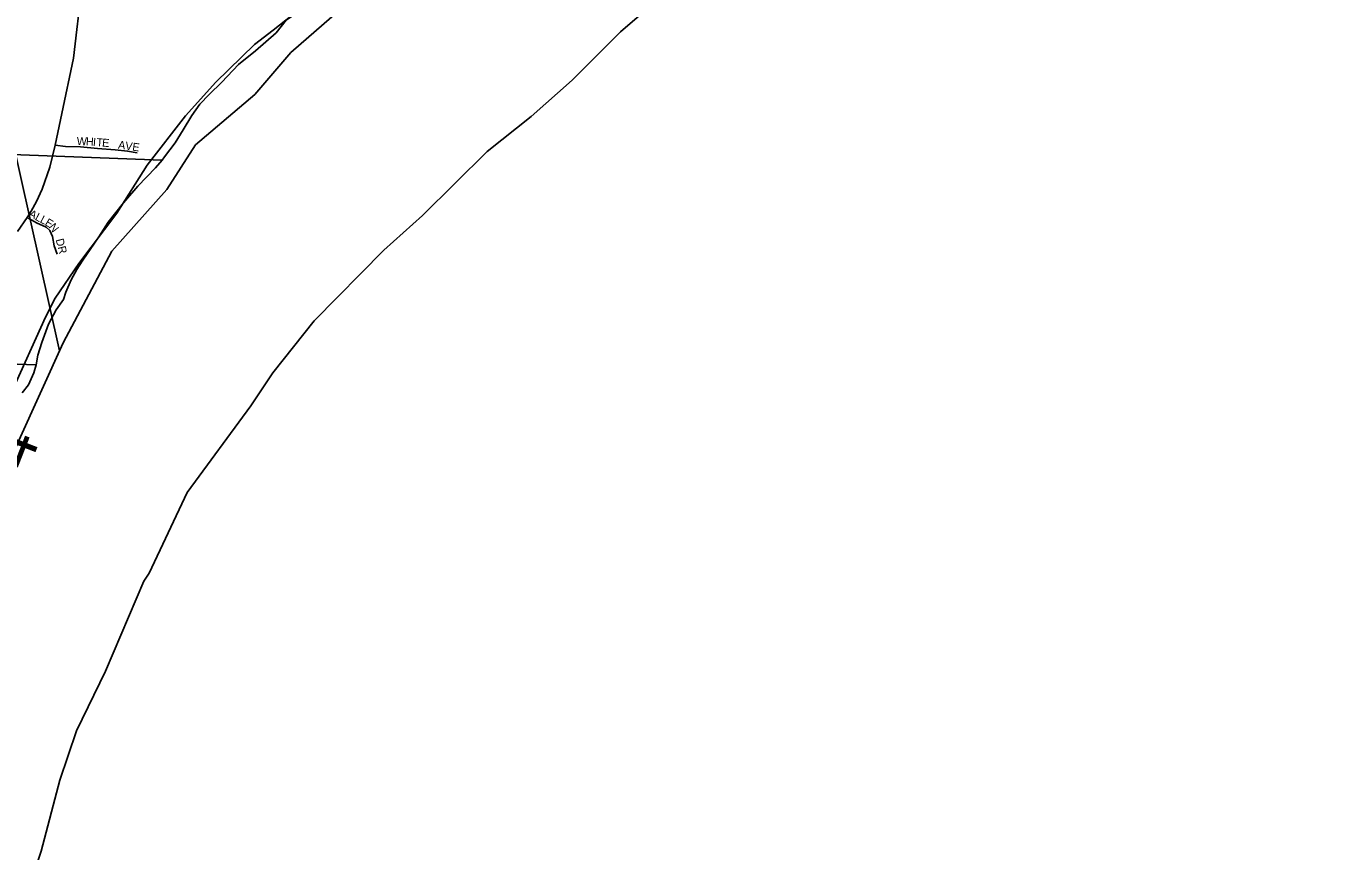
# Model space of a CAD drawing. Extents: x 1878108 to 2183446, y 146837 to 508383.
# Drawn here: x 2048929 to 2057027, y 286848 to 292008 of the extents above; entities that cross this region are included whole.
import ezdxf

# ---------------------------------------------------------------- set-up
doc = ezdxf.new("R2010")
doc.units = 0
for name, color, linetype in [('GM_X_City_Street', 7, 'Continuous'), ('GM_X_City_Street_Text', 7, 'Continuous'), ('GM_X_Corporation', 7, 'Continuous'), ('GM_X_County', 7, 'Continuous'), ('GM_X_County_Road_Text', 7, 'Continuous'), ('GM_X_Major_River', 7, 'Continuous'), ('GM_X_Section', 7, 'Continuous'), ('GM_X_State_Route', 7, 'Continuous'), ('GM_X_Township', 7, 'Continuous')]:
    doc.layers.add(name, color=color, linetype=linetype)

msp = doc.modelspace()

# ---------------------------------------------------------------- linework, layer by layer
at = {"layer": 'GM_X_City_Street'}
for points in [[(2049112, 291262.8), (2049176.3, 291253.7), (2049270.4, 291252.5), (2049376, 291242.2), (2049486.2, 291233), (2049564.2, 291225), (2049622.8, 291214.6)], [(2049123.5, 290580), (2049105.1, 290632.8), (2049094.8, 290690.1), (2049077.6, 290729.2), (2049055.8, 290748.7), (2048993.8, 290777.4), (2048936.4, 290809.5)]]:
    msp.add_lwpolyline(points, dxfattribs=at)
at = {"layer": 'GM_X_Corporation'}
msp.add_lwpolyline([(2057212.1, 297306.5), (2056735.2, 297160.2), (2056232.2, 296817.6), (2055577.6, 296152.3), (2055056.8, 295388.9), (2054757.4, 295136.5), (2053436.3, 294134.7), (2052695.8, 293625.8), (2052328.6, 293317.2), (2051352.7, 292511.8), (2050584.3, 291840.6), (2050358.8, 291578.1), (2049987.6, 291263.6), (2049808, 290985.1), (2049464.7, 290598.4), (2049161.4, 290025.3), (2049139.4, 289977), (2048708.6, 291891.2)], dxfattribs=at)
at = {"layer": 'GM_X_County'}
msp.add_lwpolyline([(2057212.1, 297306.5), (2056735.2, 297160.2), (2056232.2, 296817.6), (2055577.6, 296152.3), (2055056.8, 295388.9), (2054757.4, 295136.5), (2053436.3, 294134.7), (2052695.8, 293625.8), (2052328.6, 293317.2), (2051352.7, 292511.8), (2050584.3, 291840.6), (2050358.8, 291578.1), (2049987.6, 291263.6), (2049808, 290985.1), (2049464.7, 290598.4), (2049161.4, 290025.3), (2048195.4, 287901.3), (2047973.9, 287198), (2047804.2, 286626.9)], dxfattribs=at)
at = {"layer": 'GM_X_Major_River'}
msp.add_line((2050671.3, 292137), (2050474.3, 291981.8), dxfattribs=at)
for points in [[(2048939.1, 286593.9), (2049023.9, 286848.8), (2049139.9, 287292.2), (2049244.4, 287599.3), (2049426.6, 287972.9), (2049665.8, 288535.1), (2049697.6, 288585.4), (2049937, 289089.4), (2050334.1, 289632.2), (2050470.9, 289839.2), (2050729.1, 290163), (2051164.5, 290605.7), (2051407.1, 290823.2), (2051810.7, 291221.7), (2052085.2, 291441.2), (2052341.8, 291668.8), (2052643.9, 291970.7), (2053000, 292278.8)], [(2050474.3, 291981.8), (2050356.9, 291891.2), (2050114.3, 291655.7), (2049925.6, 291444.5), (2049685.3, 291136.8), (2049496.9, 290837.4), (2049258.6, 290521.8), (2049111.8, 290304.7), (2049050.4, 290186.2), (2048836.7, 289712.3), (2048541.3, 289222.1), (2048366.9, 288904.7), (2048122.1, 288252.2), (2047861.1, 287623.8), (2047768.7, 287268.6), (2047757, 287204.5), (2047623.5, 286636.6)]]:
    msp.add_lwpolyline(points, dxfattribs=at)
at = {"layer": 'GM_X_Section'}
for points in [[(2045974, 292455.4), (2050820.1, 292230.3), (2050754.2, 292182), (2050714.3, 292153.8), (2050554.7, 292043.3), (2050492.9, 291965), (2050363.3, 291852.5), (2050257.6, 291766.2), (2050151.9, 291655.8), (2050074.2, 291579.5), (2050014.4, 291519.3), (2049964.6, 291447.1), (2049910.9, 291356.9), (2049861.2, 291276.6), (2049795.4, 291188.4), (2049779, 291169), (2045910.6, 291315.1)], [(2049779, 291169), (2049737.7, 291120.2), (2049628, 291005.8), (2049538.4, 290901.4), (2049442.8, 290781.1), (2049385.1, 290688.9), (2049329.3, 290608.7), (2049283.5, 290542.5), (2049245.7, 290484.3), (2049212, 290420.2), (2049178.2, 290342.1), (2049164.4, 290298), (2049118.6, 290231.8), (2049068.9, 290143.6), (2049027.3, 290027.4), (2049003.5, 289949.3), (2048991.9, 289888.3), (2045832.9, 289999.9), (2045910.6, 291315.1)]]:
    msp.add_lwpolyline(points, close=True, dxfattribs=at)
msp.add_lwpolyline([(2045832.9, 289999.9), (2048991.9, 289888.3), (2048977.9, 289839.2), (2048944.2, 289763.1), (2048904.3, 289712.9)], dxfattribs=at)
at = {"layer": 'GM_X_State_Route'}
for points in [[(2048936.4, 290809.5), (2048961.7, 290848.5), (2048995, 290910.5), (2049030.3, 290987.2), (2049078.7, 291125.1), (2049112, 291262.8), (2049153.3, 291460.2), (2049226.8, 291805.7), (2049247.5, 291984.7), (2049256.6, 292072)], [(2048876.1, 290721.8), (2048936.4, 290809.5)]]:
    msp.add_lwpolyline(points, dxfattribs=at)
at = {"layer": 'GM_X_Township'}
msp.add_lwpolyline([(2057212.1, 297306.5), (2056735.2, 297160.2), (2056232.2, 296817.6), (2055577.6, 296152.3), (2055056.8, 295388.9), (2054757.4, 295136.5), (2053436.3, 294134.7), (2052695.8, 293625.8), (2052328.6, 293317.2), (2051352.7, 292511.8), (2050584.3, 291840.6), (2050358.8, 291578.1), (2049987.6, 291263.6), (2049808, 290985.1), (2049464.7, 290598.4), (2049161.4, 290025.3), (2048195.4, 287901.3), (2047973.9, 287198), (2047804.2, 286626.9)], dxfattribs=at)

# ---------------------------------------------------------------- texts
at = {"layer": 'GM_X_City_Street_Text'}
for s, rotation, p in [('W', 357.62875, (2049245.4, 291263.4)), ('H', 355.88791, (2049302.1, 291261)), ('I', 355.71194, (2049346, 291257.9)), ('T', 355.69436, (2049367.9, 291256.2)), ('E', 355.70873, (2049403, 291253.6)), ('AVE', 351.87427, (2049502.5, 291241.3)), ('A', 332.3402, (2048942.1, 290817.8)), ('L', 332.32291, (2048981.1, 290797.4)), ('L', 332.34554, (2049012.3, 290781)), ('E', 328.59116, (2049042.7, 290765.1)), ('N', 307.62191, (2049069.2, 290750)), ('DR', 284.74583, (2049114.1, 290671.1))]:
    msp.add_text(s, height=50, rotation=rotation, dxfattribs=at).set_placement(p)
at = {"layer": 'GM_X_County_Road_Text'}
msp.add_text('4', height=300, rotation=68.66849, dxfattribs=at).set_placement((2048937.8, 289213))

doc.saveas('drawing.dxf')
